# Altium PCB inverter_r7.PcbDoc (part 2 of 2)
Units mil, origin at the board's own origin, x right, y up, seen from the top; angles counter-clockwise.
Board outline 7000 x 5200 mil, 2 copper layers (Top Layer, Bottom Layer), stack 92.8 mil thick; 90 components, 75 nets, 259 pads, 1172 vias.
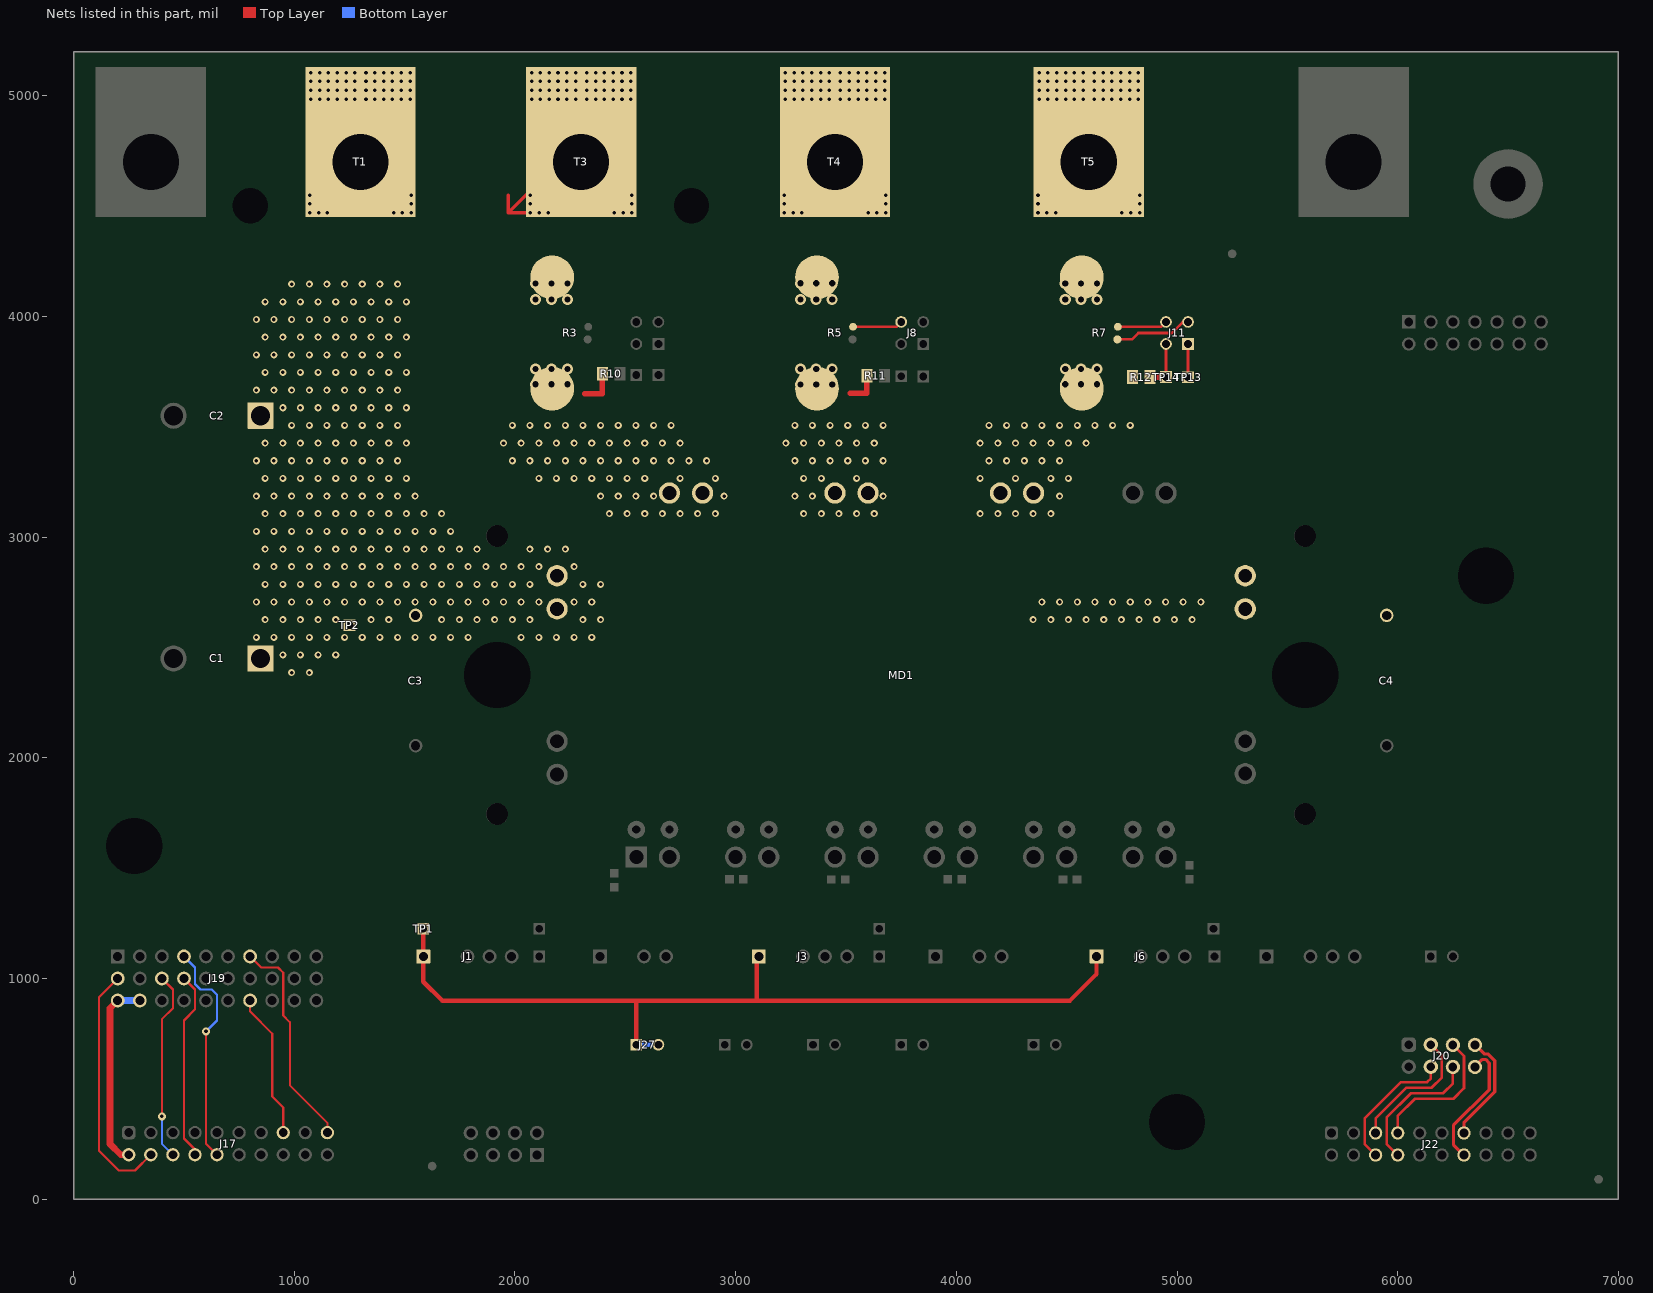
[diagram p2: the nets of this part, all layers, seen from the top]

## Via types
v1: diameter 32, hole 16, Top Layer to Bottom Layer, tented both sides, 762 vias
v2: diameter 32, hole 16, Top Layer to Bottom Layer, 369 vias
v3: diameter 50, hole 28, Top Layer to Bottom Layer, 36 vias
v4: diameter 36, hole 16, Top Layer to Bottom Layer, 5 vias

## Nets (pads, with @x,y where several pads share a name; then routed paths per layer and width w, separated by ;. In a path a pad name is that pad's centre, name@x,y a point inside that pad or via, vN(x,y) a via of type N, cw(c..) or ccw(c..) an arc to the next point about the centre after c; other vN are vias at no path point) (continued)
NetJ8_4: J8.4 R5.1 | length 227.2
  Top Layer w12: R5.1@3531.96,3952.81 3727.81,3952.81 J8.4@3750,3975
NetJ11_1: J11.1 TP13.1 | length 150.8
  Top Layer w15: TP13.1@5050,3724.21 J11.1@5050,3875
NetJ11_2: J11.2 R7.2 | length 353.1
  Top Layer w12: R7.2@4729.62,3896.09 4796.09,3896.09 4825,3925 4976.69,3925 5026.69,3975 J11.2@5050,3975
NetJ11_3: J11.3 R12.2 TP14.1 | length 222.7
  Top Layer w15: TP14.1@4950,3725 J11.3@4950,3875
  Top Layer w25: R12.2@4877.28,3725 TP14.1@4950,3725
NetJ11_4: J11.4 R7.1 | length 227.2
  Top Layer w12: R7.1@4731.96,3952.81 4927.81,3952.81 J11.4@4950,3975
NetMD1_19: MD1.19 MD1.20 R7.4 R12.1
  other v1: 4108,3106 4188,3106 4268,3106 4348,3106 4428,3106 4468,3186 4108,3266 4268,3266 4428,3266 4508,3266 4148,3346 4228,3346 4308,3346 4388,3346 4468,3346 4108,3426 4188,3426 4268,3426 4348,3426 4428,3426 4508,3426 4588,3426 4148,3506 4228,3506 4308,3506 4388,3506 4468,3506 4548,3506 4628,3506 4708,3506 4788,3506
  other v3: 4493.7,3692.46 4565.17,3692.46 4637.65,3692.46 4493.7,3761.48 4565.17,3761.48 4637.65,3761.48
NetMD1_21: MD1.21 MD1.22 R5.4 R11.1 | length 154.9
  Top Layer w25: 3518.49,3652.6 3595,3652.6 R11.1@3595,3730.95
  other v1: 3308,3106 3388,3106 3468,3106 3548,3106 3628,3106 3268,3186 3348,3186 3668,3186 3308,3266 3388,3266 3548,3266 3268,3346 3348,3346 3428,3346 3508,3346 3588,3346 3668,3346 3228,3426 3308,3426 3388,3426 3468,3426 3548,3426 3628,3426 3268,3506 3348,3506 3428,3506 3508,3506 3588,3506 3668,3506
  other v3: 3293.53,3690.95 3365,3690.95 3437.48,3690.95 3293.45,3761.48 3364.92,3761.48 3437.4,3761.48
NetMD1_23: MD1.23 MD1.24 R3.4 R10.1 | length 171.5
  Top Layer w25: 2315.23,3649.77 2396.5,3649.77 R10.1@2396.5,3740
  other v1: 2428,3106 2508,3106 2588,3106 2668,3106 2748,3106 2828,3106 2908,3106 2388,3186 2468,3186 2548,3186 2628,3186 2948,3186 2108,3266 2188,3266 2268,3266 2348,3266 2428,3266 2508,3266 2588,3266 2748,3266 2908,3266 1988,3346 2068,3346 2148,3346 2228,3346 2308,3346 2388,3346 2468,3346 2548,3346 2628,3346 2708,3346 2788,3346 2868,3346 1948,3426 2028,3426 2108,3426 2188,3426 2268,3426 2348,3426 2428,3426 2508,3426 2588,3426 2668,3426 2748,3426 1988,3506 2068,3506 2148,3506 2228,3506 2308,3506 2388,3506 2468,3506 2548,3506 2628,3506 2708,3506
  other v3: 2093.49,3692.46 2164.96,3692.46 2237.44,3692.46 2093.49,3761.48 2164.96,3761.48 2237.44,3761.48
NetR3_3: R3.3 T3.1 | length 970.5
  Top Layer w15: 1970,4550 1970,4510 1970,4470 ; T3.1@2050,4470 2010,4470 1970,4470 ; T3.1@2350,4470 2390,4470 T3.1@2430,4470 ; T3.1@2430,4550 2430,4510 T3.1@2430,4470 ; 1970,4470 2200,4700 T3.1@2430,4470
  other v2: 2070,4470 2110,4470 2150,4470 2450,4470 2490,4470 2530,4470 2070,4510 2530,4510 2070,4550 2530,4550 2075,4985 2115,4985 2155,4985 2195,4985 2235,4985 2275,4985 2325,4985 2365,4985 2405,4985 2445,4985 2485,4985 2525,4985 2075,5025 2115,5025 2155,5025 2195,5025 2235,5025 2275,5025 2325,5025 2365,5025 2405,5025 2445,5025 2485,5025 2525,5025 2075,5065 2115,5065 2155,5065 2195,5065 2235,5065 2275,5065 2325,5065 2365,5065 2405,5065 2445,5065 2485,5065 2525,5065 2075,5105 2115,5105 2155,5105 2195,5105 2235,5105 2275,5105 2325,5105 2365,5105 2405,5105 2445,5105 2485,5105 2525,5105
  other v3: 2093.49,4077.15 2164.96,4077.15 2237.44,4077.15 2093.49,4149.84 2164.96,4149.84 2237.44,4149.84
NetR5_3: R5.3 T4.1
  other v2: 3220,4470 3260,4470 3300,4470 3600,4470 3640,4470 3680,4470 3220,4510 3680,4510 3220,4550 3680,4550 3225,4985 3265,4985 3305,4985 3345,4985 3385,4985 3425,4985 3475,4985 3515,4985 3555,4985 3595,4985 3635,4985 3675,4985 3225,5025 3265,5025 3305,5025 3345,5025 3385,5025 3425,5025 3475,5025 3515,5025 3555,5025 3595,5025 3635,5025 3675,5025 3225,5065 3265,5065 3305,5065 3345,5065 3385,5065 3425,5065 3475,5065 3515,5065 3555,5065 3595,5065 3635,5065 3675,5065 3225,5105 3265,5105 3305,5105 3345,5105 3385,5105 3425,5105 3475,5105 3515,5105 3555,5105 3595,5105 3635,5105 3675,5105
  other v3: 3293.45,4077.25 3364.92,4077.25 3437.4,4077.25 3293.45,4150 3364.92,4150 3437.4,4150
NetR7_3: R7.3 T5.1
  other v2: 4370,4470 4410,4470 4450,4470 4750,4470 4790,4470 4830,4470 4370,4510 4830,4510 4370,4550 4830,4550 4375,4985 4415,4985 4455,4985 4495,4985 4535,4985 4575,4985 4625,4985 4665,4985 4705,4985 4745,4985 4785,4985 4825,4985 4375,5025 4415,5025 4455,5025 4495,5025 4535,5025 4575,5025 4625,5025 4665,5025 4705,5025 4745,5025 4785,5025 4825,5025 4375,5065 4415,5065 4455,5065 4495,5065 4535,5065 4575,5065 4625,5065 4665,5065 4705,5065 4745,5065 4785,5065 4825,5065 4375,5105 4415,5105 4455,5105 4495,5105 4535,5105 4575,5105 4625,5105 4665,5105 4705,5105 4745,5105 4785,5105 4825,5105
  other v3: 4493.49,4077.25 4564.96,4077.25 4637.44,4077.25 4493.49,4149.84 4564.96,4149.84 4637.44,4149.84
nFLT1_H: J17.6 J19.8 | length 860.6
  Top Layer w10: v4(400,375) 400,815 450,865 450,950 J19.8@400,1000
  Bottom Layer w10: v4(400,375) 400,251.52 J17.6@450,201.52
nFLT1_L: J17.8 J19.11 | length 860.6
  Top Layer w10: J19.11@500,1000 550,950 550,860 500,810 500,275 550,225 J17.8@550,201.52
nFLT2_H: J17.4 J19.2 | length 1117.5
  Top Layer w10: J19.2@200,1000 115,915 115,219.35 204.35,130 278.48,130 J17.4@350,201.52
nFLT2_L: J17.10 J19.10 | length 1031.9
  Top Layer w10: v4(600,760) 600,251.52 J17.10@650,201.52
  Bottom Layer w10: J19.10@500,1100 550,1050 550,975 575,950 626.05,950 650,926.05 650,810 v4(600,760)
OVP: J20.4 J22.6 | length 613.9
  Top Layer w12: J22.6@5900,200 5850,250 5850,365.01 6014.99,530 6132.74,530 6150,547.26 J20.4@6150,600
SDI: J17.15 J19.21 | length 660.6
  Top Layer w10: J19.21@800,900 800,850 900,750 900,465 950,415 J17.15@950,301.52
SDO: J17.19 J19.19 | length 988.2
  Top Layer w10: J19.19@800,1100 850,1050 926.41,1050 950,1026.41 950,831.81 980,801.81 980,515.78 1150,345.78 J17.19@1150,301.52
VCC1: J17.2 J19.3 J19.6 | length 869.6
  Top Layer w30: J19.3@200,900 165,865 165,250 213.48,201.52 J17.2@250,201.52
  Bottom Layer w30: J19.3@200,900 J19.6@300,900
Vdc_N: J20.8 J22.14 | length 588.6
  Top Layer w15: J22.14@6300,200 6252.38,247.62 6252.38,334.19 6414.31,496.12 6414.31,616.68 6397.99,633 6384,633 J20.8@6350,599
Vdc_P: J20.7 J22.13 | length 503.9
  Top Layer w15: J22.13@6300,300 6300,346.45 6439.31,485.76 6439.31,627.04 6408.34,658 6391,658 J20.7@6350,699
Vdcbus: C1.1 C2.1 C3.1 C4.1 MD1.15 MD1.16 MD1.25 MD1.26 T1.1 TP2.1
  other v1: 988,2386 1068,2386 948,2466 1028,2466 1108,2466 1188,2466 828,2546 908,2546 988,2546 1068,2546 1148,2546 1228,2546 1308,2546 1388,2546 1468,2546 1548,2546 1628,2546 1708,2546 1788,2546 2028,2546 2108,2546 2188,2546 2268,2546 2348,2546 868,2626 948,2626 1028,2626 1108,2626 1188,2626 1348,2626 1428,2626 1668,2626 1748,2626 1828,2626 1908,2626 1988,2626 2068,2626 2308,2626 2388,2626 4348,2626 4428,2626 4508,2626 4588,2626 4668,2626 4748,2626 4828,2626 4908,2626 4988,2626 5068,2626 828,2706 908,2706 988,2706 1068,2706 1148,2706 1228,2706 1308,2706 1388,2706 1468,2706 1548,2706 1628,2706 1708,2706 1788,2706 1868,2706 1948,2706 2028,2706 2108,2706 2268,2706 2348,2706 4388,2706 4468,2706 4548,2706 4628,2706 4708,2706 4788,2706 4868,2706 4948,2706 5028,2706 5108,2706 868,2786 948,2786 1028,2786 1108,2786 1188,2786 1268,2786 1348,2786 1428,2786 1508,2786 1588,2786 1668,2786 1748,2786 1828,2786 1908,2786 1988,2786 2068,2786 2308,2786 2388,2786 828,2866 908,2866 988,2866 1068,2866 1148,2866 1228,2866 1308,2866 1388,2866 1468,2866 1548,2866 1628,2866 1708,2866 1788,2866 1868,2866 1948,2866 2028,2866 2108,2866 2268,2866 868,2946 948,2946 1028,2946 1108,2946 1188,2946 1268,2946 1348,2946 1428,2946 1508,2946 1588,2946 1668,2946 1748,2946 1828,2946 2068,2946 2148,2946 2228,2946 828,3026 908,3026 988,3026 1068,3026 1148,3026 1228,3026 1308,3026 1388,3026 1468,3026 1548,3026 1628,3026 1708,3026 868,3106 948,3106 1028,3106 1108,3106 1188,3106 1268,3106 1348,3106 1428,3106 1508,3106 1588,3106 1668,3106 828,3186 908,3186 988,3186 1068,3186 1148,3186 1228,3186 1308,3186 1388,3186 1468,3186 1548,3186 868,3266 948,3266 1028,3266 1108,3266 1188,3266 1268,3266 1348,3266 1428,3266 1508,3266 828,3346 908,3346 988,3346 1068,3346 1148,3346 1228,3346 1308,3346 1388,3346 1468,3346 868,3426 948,3426 1028,3426 1108,3426 1188,3426 1268,3426 1348,3426 1428,3426 1508,3426 988,3506 1068,3506 1148,3506 1228,3506 1308,3506 1388,3506 1468,3506 948,3586 1028,3586 1108,3586 1188,3586 1268,3586 1348,3586 1428,3586 1508,3586 828,3666 908,3666 988,3666 1068,3666 1148,3666 1228,3666 1308,3666 1388,3666 1468,3666 868,3746 948,3746 1028,3746 1108,3746 1188,3746 1268,3746 1348,3746 1428,3746 1508,3746 828,3826 908,3826 988,3826 1068,3826 1148,3826 1228,3826 1308,3826 1388,3826 1468,3826 868,3906 948,3906 1028,3906 1108,3906 1188,3906 1268,3906 1348,3906 1428,3906 1508,3906 828,3986 908,3986 988,3986 1068,3986 1148,3986 1228,3986 1308,3986 1388,3986 1468,3986 868,4066 948,4066 1028,4066 1108,4066 1188,4066 1268,4066 1348,4066 1428,4066 1508,4066 988,4146 1068,4146 1148,4146 1228,4146 1308,4146 1388,4146 1468,4146
  other v2: 1070,4470 1110,4470 1150,4470 1450,4470 1490,4470 1530,4470 1070,4510 1530,4510 1070,4550 1530,4550 1075,4985 1115,4985 1155,4985 1195,4985 1235,4985 1275,4985 1325,4985 1365,4985 1405,4985 1445,4985 1485,4985 1525,4985 1075,5025 1115,5025 1155,5025 1195,5025 1235,5025 1275,5025 1325,5025 1365,5025 1405,5025 1445,5025 1485,5025 1525,5025 1075,5065 1115,5065 1155,5065 1195,5065 1235,5065 1275,5065 1325,5065 1365,5065 1405,5065 1445,5065 1485,5065 1525,5065 1075,5105 1115,5105 1155,5105 1195,5105 1235,5105 1275,5105 1325,5105 1365,5105 1405,5105 1445,5105 1485,5105 1525,5105
Vdcbus_Jumped: J1.1 J3.1 J6.1 J27.1 J27.2 TP1.1 | length 3956
  Top Layer w20: TP1.1@1585,1225 J1.1@1585,1100 1585,985.01 1670.01,900 ; 1671.01,900 2550,900 ; J27.1@2550,700 2550,900 ; J3.1@3095,1100 3095,905 3100,900 ; J6.1@4635,1100 4635,1020 4515,900 3100,900 ; 2550,900 3100,900
  Bottom Layer w20: J27.1@2550,700 J27.2@2650,700
VinvA: J20.5 J22.7 | length 646.1
  Top Layer w12: J22.7@6000,300 6000,377.2 6077.8,455 6252.15,455 6300,502.85 6300,649 J20.5@6250,699
VinvB: J20.6 J22.8 | length 628.9
  Top Layer w12: J22.8@6000,200 5950,250 5950,369.99 6060.01,480 6204.94,480 6250,525.06 J20.6@6250,599
VinvC: J20.3 J22.5 | length 611.7
  Top Layer w12: J22.5@5900,300 5900,365.01 6040.18,505.18 6154.16,505.18 6199.99,551.02 6199.99,650.01 J20.3@6150,700
pads on no net: FID1.1 FID2.1 FID3.1 J17.20 J19.1 J19.22 J19.23 MD1. MH1.1 MH2.1 MH3.1 MH4.1 MH5.1

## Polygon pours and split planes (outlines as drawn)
NetR3_3 on Top Layer "TOP_LAYER_NETR3_3_P006" (solid, pour order 6): 2000,5150 1948,5096.77 1948,4115 2029.73,4033.27 2277.09,4033.27 2277.09,4157.28 2500,4157.54 2624.41,4258.58 2624.41,5100.59 2575,5150
+3V3 on Top Layer "TOP_LAYER_+3V3_P063" (solid, remove dead copper, pour order 63): 5635,186.01 5706,115 5815,115 5839.31,134.71 5839.31,401.31 5985.27,547.26 6065.27,547.26 6102,583.99 6100,585.99 6100,715 5975.69,715 5635,374.31
5V on Top Layer "TOP_LAYER_5V_P059" (solid, remove dead copper, pour order 59): 6950,3500 6950,4025.9 6900.9,4075 6649.51,4075 6625,4050.49 6625,3775 6650,3775 6925,3500
NetH1_1 on Top Layer "TOP_LAYER_NETH1_1_P057" (solid, remove dead copper, pour order 57): 5550,4325 6662.87,4325 6765,4450 6765,5070 6682.75,5152.25 5537.25,5152.25 5450,5065 5450,4425
NetMD1_19 on Top Layer "TOP_LAYER_NETMD1_19_P054" (solid, remove dead copper, pour order 54): 4098.81,3075 4448.91,3075 4551.1,3177.2 4551.1,3278.28 4551.1,3327.2 4676.1,3452.2 4776.1,3452.2 4826.1,3502.2 4826.1,3664.98 4796.17,3694.91 4677.96,3694.91 4677.96,3818.93 4355.23,3818.93 4055.23,3518.93 4055.23,3127.2
5V on Top Layer "TOP_LAYER_5V_P048" (solid, remove dead copper, pour order 48): 1145.02,1170 1090,1170 1050,1130 1050,650 1200,500 1525,175 1625,75 5749.64,75 5624.64,149.86 4300.14,149.86 4048,402 2248,402 2125,525 1675,525 1450,750 1293.36,750 1170,873.36 1170,1145.02
no net on Top Layer "TOP_LAYER_NONET_P044" (solid, remove dead copper, pour order 44): 1554.49,340.78
Vdcbus on Top Layer "TOP_LAYER_VDCBUS_P034" (solid, remove dead copper, pour order 34): 1550,5150 1025,5150 975,5100 975,4228.16 750,4003.16 750,2350 800,2300 1100,2300 1275,2475 5925,2475 6000,2550 6000,2850 5750,3100 5300,3100 5075,2875 2372.23,2875 2250,3000 1815.27,3000 1550,3263.13 1550,4063 1600,4138 1600,5100
HV_GND on Top Layer "TOP_LAYER_HV_GND_P030" (solid, remove dead copper, pour order 30): 80.76,5150 50,5119.24 50,4498.12 50,1700 196.8,1553.2 1942.92,1553.2 1999.73,1610 2155,1610 2445,1900 4964.58,1900 5249.67,1700 5800,1700 6000,1900 6000,2199.99 5924.99,2275 1375,2275 1200,2100 721.84,2100 577.54,2244.3 577.54,4080.7 650,4153.16 650,5115 615,5150
NetR7_3 on Top Layer "TOP_LAYER_NETR7_3_P010" (solid, pour order 10): 4300,5150 4250,5100 4250,4149.71 4366.44,4033.27 4677.09,4033.27 4677.09,4157.28 4869.05,4157.28 4930,4218.23 4930,5120 4900,5150
NetR5_3 on Top Layer "TOP_LAYER_NETR5_3_P008" (solid, pour order 8): 3150.01,5150.01 3100,5100 3100,4147.28 3214.02,4033.27 3477.09,4033.27 3477.09,4157.28 3670.3,4157.28 3775,4261.99 3775,5100.01 3725,5150.01
NetMD1_21 on Top Layer "TOP_LAYER_NETMD1_21_P002" (solid, remove dead copper, pour order 2): 3200,3816.73 3154.12,3770.86 3154.13,3420.87 3225,3350 3225,3125 3275,3075 3675,3075 3725,3125 3725,3602.09 3634.37,3692.72 3472.84,3692.72 3472.84,3816.73
NetMD1_23 on Top Layer "TOP_LAYER_NETMD1_23_P000" (solid, remove dead copper, pour order 0): 1975,3816.73 1923.42,3765.15 1923.42,3380.64 2106.25,3197.8 2300.23,3197.8 2423.03,3075 2930,3075 2975,3120 2975,3284.13 2709.13,3550 2605,3550 2462.28,3692.72 2277.09,3692.72 2277.09,3816.73
5V_GND on Bottom Layer "BOTTOM_LAYER_5V_GND_P061" (solid, remove dead copper, pour order 61): 6950,3500 6950,4025 6900,4075 6524.51,4075 6500,4050.49 6500,3875 6550,3875 6925,3500
NetH1_1 on Bottom Layer "BOTTOM_LAYER_NETH1_1_P055" (solid, remove dead copper, pour order 55): 5550,4325 6291.48,4325 6662.87,4325 6765,4450 6765,5070 6682.75,5152.25 5537.25,5152.25 5450,5065 5450,4425
DGND on Bottom Layer "BOTTOM_LAYER_DGND_P050" (solid, remove dead copper, pour order 50): 200,900 149.35,900 149.35,897.04 100,847.69 100,179.35 179.35,100 1200,100 1247.57,147.57 1255,147.57 1255,385 1190,450 915,725 915,904.45 869.45,950 250,950
5V_GND on Bottom Layer "BOTTOM_LAYER_5V_GND_P038" (solid, remove dead copper, pour order 38): 1030,1170 970,1170 950,1150 950,750 1200,500 1525,175 1625,75 2175,75 5747.14,75 5627.14,149.86 4300.65,149.86 4049.5,400 2250,400 2125,525 1675,525 1374.02,825.98 1073.96,825.98 1050,849.94 1050,1150
AGND on Bottom Layer "BOTTOM_LAYER_AGND_P036" (solid, remove dead copper, pour order 36): 5973.2,715 5650,415.51 5650,170.96 5691.55,129.49 6875,150.44 6875,3450 6475,3850 6475,4050.49 6450.49,4075 5995,4075 5950,4030 5950,3780 6600,3130 6600,861.81 6453.19,715
HV_GND on Bottom Layer "BOTTOM_LAYER_HV_GND_P032" (solid, remove dead copper, pour order 32): 80.76,5150 50,5119.24 50,1700 196.8,1553.2 2093.2,1553.2 2440,1900 4963.78,1900 5249.67,1700 5800,1700 6000,1900 6000,2200 5924.98,2275 1375,2275 1200,2100 721.84,2100 577.54,2244.3 577.54,4080.7 650,4153.16 650,5115 615,5150
Vdcbus on Bottom Layer "BOTTOM_LAYER_VDCBUS_P024" (solid, remove dead copper, pour order 24): 1550,5150 1025,5150 975,5100 975,4228.16 750,4003.16 750,2350 800,2300 1100,2300 1275,2475 5925,2475 6000,2550 6000,2850 5750,3100 5300,3100 5075,2875 2372.23,2875 2250,3000 1815.27,3000 1550,3263.13 1550,4063 1600,4138 1600,5100.04
NetMD1_19 on Bottom Layer "BOTTOM_LAYER_NETMD1_19_P022" (solid, remove dead copper, pour order 22): 4098.81,3075 4448.91,3075 4551.1,3177.2 4551.1,3327.2 4676.1,3452.2 4776.1,3452.2 4826.1,3502.2 4826.1,3664.98 4796.17,3694.91 4677.09,3694.91 4677.09,3818.93 4355.23,3818.93 4055.23,3518.93 4055.23,3127.2
NetMD1_21 on Bottom Layer "BOTTOM_LAYER_NETMD1_21_P020" (solid, remove dead copper, pour order 20): 3200,3816.73 3154.12,3770.86 3154.13,3420.87 3225,3350 3225,3125 3275,3075 3675,3075 3725,3125 3725,3602.09 3634.37,3692.72 3472.84,3692.72 3472.84,3816.73
NetMD1_23 on Bottom Layer "BOTTOM_LAYER_NETMD1_23_P018" (solid, remove dead copper, pour order 18): 1975,3816.73 1923.42,3765.15 1923.42,3380.64 2105.15,3198.9 2299.13,3198.9 2423.03,3075 2930,3075 2975,3120 2975,3284.13 2709.13,3550 2605,3550 2462.28,3692.72 2277.09,3692.72 2277.09,3816.73
NetR7_3 on Bottom Layer "BOTTOM_LAYER_NETR7_3_P016" (solid, pour order 16): 4300,5150 4250,5100 4250,4150.66 4367.4,4033.27 4677.09,4033.27 4677.09,4157.28 4869.05,4157.28 4930,4218.23 4930,5120 4899.99,5150
NetR5_3 on Bottom Layer "BOTTOM_LAYER_NETR5_3_P014" (solid, pour order 14): 3150.01,5150.01 3100,5100 3100,4147.28 3214.02,4033.27 3477.09,4033.27 3477.09,4157.28 3670.3,4157.28 3775,4261.99 3775,5100.01 3725.01,5150
NetR3_3 on Bottom Layer "BOTTOM_LAYER_NETR3_3_P012" (solid, pour order 12): 2000,5150 1948,5096.77 1948,4115 2029.73,4033.27 2277.09,4033.27 2277.09,4157.28 2500,4157.54 2624.41,4258.58 2624.41,5100.59 2575,5150

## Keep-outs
Keep-Out Layer:
  text ".Layer_Name" at 577,-858.49 h60

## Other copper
Top Layer:
  text ".Layer_Name" at 577,-858.49 h60
Bottom Layer:
  text ".Layer_Name" at 577,-858.49 h60

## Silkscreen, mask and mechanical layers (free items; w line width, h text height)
Top Overlay:
  lines w6: 75,1000 75,1811.42 6325,1811.42 ; 1225,1000 6325,1000 6325,1410 6325,1759.63 6325,1810 ; 2400,499.35 2400,800 6454.13,800 6454.13,499.35 5100,500 ; 2400,500 3600,500 4900,500 ; 2400,3782.48 2400,4200 3235,4200 ; 2401.09,3781.97 3222.6,3781.97 ; 3558.23,3780 4440.5,3780 ; 3558.23,4200 4440.5,4200 ; 4758.03,4200 6800,4200 6800,3775 4780.55,3773.91
  lines w10: 1255,2450 1340,2450 ; 1290,3550 1380,3550 ; 1300,2411.45 1300,2488.55 ; 1335,3511.45 1335,3595.26
  lines w20: 50,4225 225,4225 1650,4225 1650,5150 ; 5000,5150 5000,4305 1850,4305 1850,5150 ; 1850,5150 1850,5150
  lines w40: 100,1350 1325,1350 1325,877 1827,375 4810.04,375 ; 5200,375.36 5324.64,375.36 5800,850 5843.81,893.81 6325,893.81 6400.2,969.01 6400.21,1850 ; 6400,1850 6400,2650 ; 6400,3000 6400,3080.21 5750,3735 5750,4250 5750,4325 6950,4325
  text "HOT SURFACE" at 4247.67,5127 h72.83 r180
  text "HIGH VOLTAGE" at 3098.28,5125 h72.83 r180
  text "CAUTION" at 4206.99,5040 h90 r180
  text "DANGER" at 3035,5035 h100 r180
  text "VOUT-A" at 2000,4600 h72.83 r90
  text "VOUT-B" at 3150,4600 h72.83 r90
  text "VOUT-C" at 4300,4600 h72.83 r90
  text "EARTH" at 5500,4595.71 h72.83 r90
  text "DC -" at 495.6,4425 h80 r180
  text "DC +" at 1331,4425 h80 r180
  text "HIGH VOLTAGE" at 6331.88,4415 h80 r180
  text "AC OUTPUT --> Max 25A sine (rms)" at 4268,4400 h90 r180
  text "-->  450Vdc / 25A" at 915.97,4317.23 h72.83 r180
  text "DC INPUT" at 1262,4317.23 h72.83 r180
  text "LOW VOLTAGE" at 6328,4280 h80 r180
  text "Slot for Current Sense Board" at 5665.34,4162.21 h72.83 r180
  text "IsoC_15V-" at 4950,3599.98 h50 r270
  text "IsoC_15V+" at 5050,3599.98 h50 r270
  text "IsoB_15V-" at 3740,3598.34 h50 r270
  text "IsoB_15V+" at 3840,3598.34 h50 r270
  text "IsoA_15V+" at 2635,3588 h50
  text "IsoA_15V-" at 2382,3587 h50
  text "LOW VOLTAGE" at 5990,3555 h80 r315
  text "HIGH VOLTAGE" at 5895,3455 h80 r315
  text "'.PRJ_Number'.PCB_Rev" at 3919.5,2650 h70 r180
  text "TRACTION INVERTER" at 3933.5,2550 h120 r180
  text "HIGH VOLTAGE" at 6305,2510 h80 r270
  text "LOW VOLTAGE" at 6440,2510 h80 r270
  text "DANGER - HIGH VOLTAGE" at 3562.5,2253 h100 r180
  text "READ USER GUIDE BEFORE USE" at 5375,2250 h100 r180
  text "AL" at 3125,1800 h72.83 r180
  text "AH" at 2670,1795 h72.83 r180
  text "BH" at 3565,1795 h72.83 r180
  text "BL" at 4014.15,1795 h72.83 r180
  text "CH" at 4475,1795 h72.83 r180
  text "CL" at 4915,1790 h72.83 r180
  text "HIGH VOLTAGE" at 980,1445 h80 r180
  text "Slot for Inverter Gate Driver Board" at 4075,1385 h72.83 r180
  text "LOW VOLTAGE" at 970,1300 h80 r180
  text "IsoA_15V+" at 2220,1297.57 h50 r180
  text "IsoB_15V+" at 3750,1290 h50 r180
  text "IsoC_15V+" at 5270,1290 h50 r180
  text "IsoA_15V-" at 2215.94,980 h50 r180
  text "IsoB_15V-" at 3750,980 h50 r180
  text "IsoC_15V-" at 5270,975 h50 r180
  text "HIGH VOLTAGE" at 6305,975 h80 r180
  text "LOW VOLTAGE" at 6380,861.81 h80 r180
  text "Slot for Voltage Sense Board" at 5490,745 h72.83 r180
  text "HIGH VOLTAGE" at 1825,510 h80 r135
  text "HIGH VOLTAGE" at 3101.18,465 h80 r180
  text "HIGH VOLTAGE" at 4815.04,465 h80 r180
  text "LOW VOLTAGE" at 1726.01,410 h80 r135
  text "LOW VOLTAGE" at 3101.18,330 h80 r180
  text "LOW VOLTAGE" at 4810.04,325.49 h80 r180
  text ".Layer_Name" at 577,-858.49 h60
Bottom Overlay:
  text ".Layer_Name" at 577,-858.49 h60
Top Paste:
  text ".Layer_Name" at 577,-858.49 h60
Bottom Paste:
  text ".Layer_Name" at 577,-858.49 h60
Top Solder:
  text ".Layer_Name" at 577,-858.49 h60
  text ".Layer_Name" at 577,-858.49 h60
Bottom Solder:
  text ".Layer_Name" at 577,-858.49 h60
Drill Guide:
  text ".Layer_Name" at 577,-858.49 h60
M1 Board Outline:
  the board outline again, w10
  text ".Layer_Name" at 577,-858.49 h60
M2 Board Dimensions:
  rectangle: 0,-275 125,-150
  rectangle: 125,-400 500,-275
  lines w7: 0,-275 1000,-275 ; 125,-400 125,-150 ; 250,-400 250,-150 ; 500,-400 500,-150 ; 750,-400 750,-150 ; 0,-400 1000,-400 1000,-150 0,-150 0,-400
  text ".Layer_Name" at 577,-858.49 h60
M3 3D STEP Top:
  text ".Layer_Name" at 577,-858.49 h60
M4 3D STEP Bottom:
  text ".Layer_Name" at 577,-858.49 h60
M5 Assembly Top:
  lines w10: -292,-930.17 6308,-930.17 ; -292,-726.83 6310,-726.83 ; -292,-523.5 -292,-1133.5 3713,-1133.5 6310,-1133.5 6310,-523.5 -291.5,-523.5 -291.5,-1133.5 1284,-1133.5 ; 2173,-1133.5 2173,-523.5 ; 3440,-726.83 3440,-523.5 ; 4280,-726.83 4280,-523.5 ; 4902,-1140 4902,-937.17
  text "COMPONENTS MARKED 'DNP' SHOULD NOT BE POPULATED." at 1153.5,-318.5 h60
  text "ASSEMBLY VARIANT:" at 1153,-434 h60
  text ".VariantName" at 2189,-434 h60
  text "PCB VIEWED FROM TOP SIDE" at -228.5,-655.67 h60
  text "BOARD #:" at 2248,-655.67 h60
  text ".PRJ_Number" at 2793.5,-655.67 h60
  text "REV:" at 3638,-655.67 h60
  text ".PCB_Rev" at 3929.5,-655.67 h60
  text "SVN REV:" at 4476,-655.67 h60
  text ".VersionControl_RevNumber" at 4982,-655.67 h60
  text "TID #:" at 2248,-859 h60
  text ".TID" at 2793.5,-859 h60
  text "PLOT NAME =" at -228.5,-1064.34 h60
  text ".plot_File_Name" at 577,-1064.34 h60
  text "GENERATED    :" at 2250,-1064.34 h60
  text ".Print_Date" at 3119.5,-1064.34 h60
  text ".Print_Time" at 3848.5,-1064.34 h60
  text "TEXAS INSTRUMENTS" at 5113,-1064.34 h60
M6 Assembly Bottom:
  lines w10: -292.5,-727.33 6309.5,-727.33 ; -290.5,-930.67 6309.5,-930.67 ; 1115.5,-1140.5 1115.5,-937.67 ; 1737.5,-727.33 1737.5,-524 ; 2577.5,-727.33 2577.5,-524 ; 3844.5,-1134 3844.5,-524 ; 4733.5,-1134 6309,-1134 6309,-524 -292.5,-524 -292.5,-1134 2304.5,-1134 6309.5,-1134 6309.5,-524
  text "COMPONENTS MARKED 'DNP' SHOULD NOT BE POPULATED." at 6102,-318 h60
  text ".VariantName" at 5058,-434 h60
  text "ASSEMBLY VARIANT:" at 6097,-434 h60
  text ".VersionControl_RevNumber" at 1035.5,-656.17 h60
  text "SVN REV:" at 1541.5,-656.17 h60
  text ".PCB_Rev" at 2088,-656.17 h60
  text "REV:" at 2379.5,-656.17 h60
  text ".PRJ_Number" at 3224,-656.17 h60
  text "BOARD #:" at 3769.5,-656.17 h60
  text "PCB VIEWED FROM BOTTOM SIDE" at 6246,-656.17 h60
  text ".TID" at 3224,-859.5 h60
  text "TID #:" at 3769.5,-859.5 h60
  text "TEXAS INSTRUMENTS" at 904.5,-1064.84 h60
  text ".Print_Time" at 2169,-1064.84 h60
  text ".Print_Date" at 2898,-1064.84 h60
  text "GENERATED    :" at 3767.5,-1064.84 h60
  text ".plot_File_Name" at 5440.5,-1064.84 h60
  text "PLOT NAME =" at 6246,-1064.84 h60
M9 Title Sheet:
  drawing of 57 lines, arcs and shapes, not listed
  text "1" at 739.84,8036.5 h70
  text "2" at 3235.5,8036.5 h70
  text "3" at 5724.84,8036.5 h70
  text "4" at 8231.51,8036.5 h70
  text "5" at 10730.5,8036.5 h70
  text "6" at 13235.5,8036.5 h70
  text "A" at -416.5,6893.5 h70
  text "A" at 14383.5,6893.5 h70
  text "B" at -416.5,4513.5 h70
  text "B" at 14383.5,4513.5 h70
  text "C" at -416.5,2138.5 h70
  text "C" at 14383.5,2138.5 h70
  text "PROJECT TITLE:" at 11343.5,277.5 h45
  text ".PRJ_Title" at 11393.5,144.17 h70
  text "DESIGNED FOR:" at 11343.5,-23.5 h45
  text ".PRJ_Customer" at 11393.5,-163.5 h70
  text "D" at -416.5,-231.5 h70
  text "D" at 14383.5,-231.5 h70
  text "FILE NAME:" at 11343.5,-323.5 h45
  text ".PCB_File_Name_No_Path" at 11393.5,-443.5 h70
  text "Texas Instruments (TI) and/or its licensors do not warrant the accuracy or completeness of this specification" at 6374,-605.34 h45
  text "ENGINEER:" at 11343.5,-613.5 h45
  text "LAYOUT BY:" at 12848.5,-613.5 h45
  text "or any information contained therein. TI and/or its licensors do not warrant that this design will meet" at 6329.01,-718 h45
  text ".PRJ_Engineer" at 11393.5,-768.49 h70
  text ".PCB_Layout" at 12899,-768.49 h70
  text "the specifications, will be suitable for your application or fit for any particular purpose, or will operate in" at 6329.01,-830.67 h45
  text ".Layer_Name" at 577,-858.49 h60
  text "ALTIUM DESIGNER VERSION:" at 12848.5,-923.5 h45
  text "an implementation. TI and/or its licensors do not warrant that the design is production worthy. You should" at 6329.01,-943.33 h45
  text "completely validate and test your design implementation to confirm the system functionality for your application." at 6374,-1056 h45
  text ".print_Scale" at 11393.5,-1056.83 h70
  text ".Application_BuildNumber" at 12899,-1056.83 h70
  text "1" at 739.84,-1263.5 h70
  text "2" at 3235.5,-1263.5 h70
  text "3" at 5724.84,-1263.5 h70
  text "4" at 8231.51,-1263.5 h70
  text "5" at 10730.5,-1263.5 h70
  text "6" at 13235.5,-1263.5 h70
M10 Fab Notes:
  drawing of 189 lines, arcs and shapes, not listed
  text "DESIGN INFORMATION" at 12382.02,6356.17 h60
  text "MIN. TRACK WIDTH:" at 11737.46,6224.05 h60
  text "8" at 12833.7,6224.05 h60
  text "MIL" at 12988.46,6224.05 h60
  text "MIN. CLEARANCE:" at 11737.46,6099.92 h60
  text "0.2" at 12773.7,6099.93 h60
  text "mm" at 12988.46,6099.92 h60
  text "MIN. VIA PAD SIZE:" at 11737.46,5975.8 h60
  text "24" at 12803.71,5975.8 h60
  text "MIL" at 12988.46,5975.8 h60
  text "0.05mm (2MIL)" at 12432.46,5845.9 h60
  text "MINIMUM ANNULAR RING" at 11408.23,5837.67 h60
  text "EXTERNAL" at 13140.46,5837.67 h60
  text "PER" at 11608.23,5727.55 h60
  text "IPC-D-275 CLASS 2 LEVEL C" at 11828.23,5727.54 h60
  text "MIL, HOLES" at 13316.46,5627.07 h60
  text "+/-" at 12924,5618.48 h60
  text "+/-" at 13778,5618.48 h60
  text "REGISTRATION TOLERANCES:" at 11408.23,5617.42 h60
  text "METAL" at 12608,5617.42 h60
  text "5" at 13184.2,5617.42 h60
  text "3" at 14017.2,5617.42 h60
  text "MIL" at 14133.46,5617.42 h60
  text "HOLE SIZE TOLERANCE (UNLESS OTHERWISE SPECIFIED):" at 11408.23,5519.1 h60
  text "+/-" at 13778,5516.23 h60
  text "3" at 14017.2,5515.17 h60
  text "MIL" at 14133.46,5515.17 h60
  text "MATERIAL:" at 11333.46,5377.52 h60
  text "FR-4 High Tg" at 12319.9,5249 h60
  text "X" at 12175.46,5241.01 h60
  text "FR-408" at 11754.46,5236.49 h60
  text "OTHER" at 13242.46,5236.49 h60
  text "X" at 11950,5100 h60
  text "93 MIL (2.4mm) +/-10%" at 12074.56,5093.46 h60
  text "THICKNESS:" at 11408.23,5085.24 h60
  text "OTHER" at 13359.46,5085.24 h60
  text "TOLERANCE:" at 11408.23,4946.92 h60
  text "X" at 12256.46,4946.92 h60
  text "ANSI IPC-6012 TYPE 3 CLASS 2" at 12434.48,4946.92 h60
  text "OTHER +/-" at 12434.46,4802.73 h60
  text "BOW & TWIST:" at 11408.23,4657.54 h60
  text "X" at 12256.46,4657.54 h60
  text "ANSI IPC-6012 TYPE 3 CLASS 2" at 12434.48,4657.54 h60
  text "OTHER +/-" at 12434.46,4510.85 h60
  text "DRILLING:" at 11333.46,4380.23 h60
  text "NC_DRILL FILES" at 13094.46,4275.04 h60
  text "REFERENCE:" at 11408.23,4271.1 h60
  text "X" at 12065.46,4271.01 h60
  text "AS SHOWN" at 12243.46,4271.1 h60
  text "X" at 12966.46,4271.1 h60
  text "OTHER" at 13392.46,4128.85 h60
  text "PTH COPPER THICKNESS:" at 11407.91,4125.32 h60
  text "X" at 12547.14,4125.32 h60
  text "20-30 um" at 12675.14,4125.32 h60
  text "BOARD FINISH:" at 11333.46,3977.73 h60
  text "SILKSCREEN:" at 11488.68,3867.6 h60
  text "X" at 12446.46,3867.6 h60
  text "TOP" at 12563.46,3867.6 h60
  text "BOTTOM" at 13074.46,3867.6 h60
  text "SILKSCREEN COLOR:" at 11488.68,3712.41 h60
  text "X" at 12445.46,3712.41 h60
  text "WHITE" at 12563.46,3712.41 h60
  text "OTHER" at 13074.46,3712.41 h60
  text "X" at 12576.46,3568.96 h60
  text "GREEN" at 12694.46,3568.96 h60
  text "OTHER" at 13312.46,3568.96 h60
  text "SOLDER RESIST COLOR:" at 11488.68,3562.1 h60
  text "X" at 12576.46,3414.71 h60
  text "MATTE" at 12694.46,3414.71 h60
  text "SEMI-GLOSS" at 13312,3414.07 h60
  text "IMMERSION GOLD (ENIG)" at 12394.46,3241.94 h60
  text "ENEPIG" at 13732,3234.72 h60
  text "SURFACE FINISH:" at 11333.46,3233.72 h60
  text "X" at 12225,3233.72 h60
  text "HASL LEAD FREE" at 13475,3100 h60
  text "IMM. TIN/SILVER OR EQUIV" at 11663,3096.4 h60
  text "OTHER" at 13094.46,3092.47 h60
  text "ARRAY/PANEL:" at 11333.46,2937.09 h60
  text "CUT AND TRIM PER M1 BOARD OUTLINE" at 12394.46,2928.87 h60
  text "N.C. ROUTE" at 12394.46,2792.9 h60
  text "X" at 13082.46,2792.9 h60
  text "V. SCORE" at 13260.46,2792.9 h60
  text "CERTIFICATION:" at 11333.46,2663.77 h60
  text "MATERIALS AND WORKMANSHIP FOR ALL PCBS" at 12058.46,2663.77 h60
  text "TO MEET OR EXCEED THE REQUIREMENTS OF:" at 12058.46,2569.71 h60
  text "X" at 11695.97,2441.08 h60
  text "ANSI IPC-A-600F CLASS ->" at 11823.96,2441.08 h60
  text "X" at 13471.97,2441.08 h60
  text "2" at 13581.96,2441.08 h60
  text "1" at 13266.96,2439.58 h60
  text "3" at 13935.96,2439.58 h60
  text "X" at 12507.97,2293.39 h60
  text "RoHS" at 12635.96,2293.39 h60
  text "OTHER" at 13280.36,2293.39 h60
  text "PER ORDER" at 13677.42,2293.39 h60
  text "ALL BOARDS MUST MEET OR EXCEED UL94-V0 REQUIREMENTS." at 11361,2139.57 h60
  text "PCB MUST BEAR THE UL94V-0 UL REGISTERED MATERIAL ID NUMBER" at 11361,2023.5 h60
  text "ADDITIONAL REQUIREMENTS:" at 11333.46,1854.08 h60
  text "MICROSECTION:" at 11408.23,1746.95 h60
  text "YES" at 12313.96,1746.95 h60
  text "X" at 12593.5,1602.62 h60
  text "REQUIRED" at 13175.46,1602.62 h60
  text "BARE BOARD ELEC. TEST:" at 11408.23,1599.76 h60
  text "NONE" at 12713.96,1599.76 h60
  text "PER ORDER" at 13767.46,1599.76 h60
  text "XX MIL VIAS REQUIRE NON-CONDUCTIVE FILL AND PLANARIZE" at 11576.38,1394.82 h59
  text "XX MIL VIAS REQUIRE CONDUCTIVE FILL AND PLANARIZE" at 11584.38,1290.84 h60
  text "OUTER XX MIL TRACES REQUIRE 50 OHM SINGLE-ENDED IMPEDANCE" at 11583.39,1127.46 h58
  text "LAYER 2 & 3 (INNER LAYERS) XX MIL WIDE, XX MIL SPACE / TRACES REQUIRE 100 OHM DIFFERENTIAL IMPEDANCE" at 11575.39,891.74 h60
  text ".Layer_Name" at 577,-858.49 h60
M11 Gerber Information:
  lines w10: -292,-930.17 6308,-930.17 ; -292,-726.83 6310,-726.83 ; -292,-523.5 -292,-1133.5 3713,-1133.5 6310,-1133.5 6310,-523.5 -291.5,-523.5 -291.5,-1133.5 1284,-1133.5 ; 2173,-1133.5 2173,-523.5 ; 3440,-726.83 3440,-523.5 ; 4280,-726.83 4280,-523.5 ; 4902,-1140 4902,-937.17
  text "ALL ARTWORK VIEWED FROM TOP SIDE" at -228.5,-655.67 h60
  text "BOARD #:" at 2248,-655.67 h60
  text ".PRJ_Number" at 2793.5,-655.67 h60
  text "REV:" at 3638,-655.67 h60
  text ".PCB_Rev" at 3929.5,-655.67 h60
  text "SVN REV:" at 4476,-655.67 h60
  text ".VersionControl_RevNumber" at 4982,-655.67 h60
  text "LAYER NAME =" at -228.5,-858.49 h60
  text "TID #:" at 2248,-859 h60
  text ".TID" at 2793.5,-859 h60
  text "PLOT NAME =" at -228.5,-1064.34 h60
  text ".plot_File_Name" at 577,-1064.34 h60
  text "GENERATED    :" at 2250,-1064.34 h60
  text ".Print_Date" at 3119.5,-1064.34 h60
  text ".Print_Time" at 3848.5,-1064.34 h60
  text "TEXAS INSTRUMENTS" at 5113,-1064.34 h60
M12 Stackup:
  drawing of 191 lines, arcs and shapes, not listed
  text "Layer" at 9760.58,7397.5 h60
  text "Name" at 10170.49,7397.5 h60
  text "Material" at 11100.23,7397.5 h60
  text "Thickness" at 11960,7397.5 h60
  text "Constant" at 12609.84,7397.5 h60
  text "Board Layer Stack" at 13179.7,7397.5 h60
  text "1" at 9760.58,7277.5 h60
  text "Top Overlay" at 10170.49,7277.5 h60
  text "2" at 9760.58,7157.5 h60
  text "Top Solder" at 10170.49,7157.5 h60
  text "Solder Resist" at 11100.23,7157.5 h60
  text "0.40mil" at 11960,7157.5 h60
  text "3.5" at 12609.84,7157.5 h60
  text "3" at 9760.58,7037.5 h60
  text "Top Layer" at 10170.49,7037.5 h60
  text "Copper" at 11100.23,7037.5 h60
  text "2.80mil" at 11960,7037.5 h60
  text "4" at 9760.58,6917.5 h60
  text "Dielectric1" at 10170.49,6917.5 h60
  text "FR-4" at 11100.23,6917.5 h60
  text "87.20mil" at 11960,6917.5 h60
  text "4.8" at 12609.84,6917.5 h60
  text "5" at 9760.58,6797.5 h60
  text "Bottom Layer" at 10170.49,6797.5 h60
  text "Copper" at 11100.23,6797.5 h60
  text "2.80mil" at 11960,6797.5 h60
  text "6" at 9760.58,6677.5 h60
  text "Bottom Solder" at 10170.49,6677.5 h60
  text "Solder Resist" at 11100.23,6677.5 h60
  text "0.40mil" at 11960,6677.5 h60
  text "3.5" at 12609.84,6677.5 h60
  text "7" at 9760.58,6557.5 h60
  text "Bottom Overlay" at 10170.49,6557.5 h60
  text ".Layer_Name" at 577,-858.49 h60
M13 Component Bodies Top:
  text ".Layer_Name" at 577,-858.49 h60
M14 Component Bodies Bottom:
  text ".Layer_Name" at 577,-858.49 h60
M15 Courtyards Top:
  text ".Layer_Name" at 577,-858.49 h60
M16 Courtyards Bottom:
  text ".Layer_Name" at 577,-858.49 h60
Drill Drawing:
  drawing of 184 lines, arcs and shapes, not listed
  text "Symbol" at 7996.57,3595.92 h72
  text "Quantity" at 8297.14,3595.92 h72
  text "Finished Hole Size" at 8629.14,3595.92 h72
  text "Plated" at 9265.7,3595.92 h72
  text "Hole Type" at 9524.84,3595.92 h72
  text "Drill Layer Pair" at 9900,3595.92 h72
  text "Hole Tolerance" at 10624.33,3595.92 h72
  text "4" at 8297.14,3471.6 h60
  text "98.43mil (2.500mm)" at 8629.14,3471.6 h60
  text "NPTH" at 9265.7,3471.6 h60
  text "Round" at 9524.84,3471.6 h60
  text "Top Layer - Bottom Layer" at 9900,3471.6 h60
  text "2" at 8297.14,3347.28 h60
  text "160.00mil (4.064mm)" at 8629.14,3347.28 h60
  text "NPTH" at 9265.7,3347.28 h60
  text "Round" at 9524.84,3347.28 h60
  text "Top Layer - Bottom Layer" at 9900,3347.28 h60
  text "B" at 7971.29,3337.29 h55.25
  text "3" at 8297.14,3222.96 h60
  text "254.00mil (6.452mm)" at 8629.14,3222.96 h60
  text "NPTH" at 9265.7,3222.96 h60
  text "Round" at 9524.84,3222.96 h60
  text "Top Layer - Bottom Layer" at 9900,3222.96 h60
  text "C" at 7971.29,3212.97 h55.25
  text "2" at 8297.14,3098.64 h60
  text "301.00mil (7.645mm)" at 8629.14,3098.64 h60
  text "NPTH" at 9265.7,3098.64 h60
  text "Round" at 9524.84,3098.64 h60
  text "Top Layer - Bottom Layer" at 9900,3098.64 h60
  text "1136" at 8297.14,2974.32 h60
  text "16.00mil (0.406mm)" at 8629.14,2974.32 h60
  text "PTH" at 9265.7,2974.32 h60
  text "Round" at 9524.84,2974.32 h60
  text "Top Layer - Bottom Layer" at 9900,2974.32 h60
  text "36" at 8297.14,2850 h60
  text "28.00mil (0.711mm)" at 8629.14,2850 h60
  text "PTH" at 9265.7,2850 h60
  text "Round" at 9524.84,2850 h60
  text "Top Layer - Bottom Layer" at 9900,2850 h60
  text "38" at 8297.14,2725.68 h60
  text "35.04mil (0.890mm)" at 8629.14,2725.68 h60
  text "PTH" at 9265.7,2725.68 h60
  text "Round" at 9524.84,2725.68 h60
  text "Top Layer - Bottom Layer" at 9900,2725.68 h60
  text "12" at 8297.14,2601.36 h60
  text "37.99mil (0.965mm)" at 8629.14,2601.36 h60
  text "PTH" at 9265.7,2601.36 h60
  text "Round" at 9524.84,2601.36 h60
  text "Top Layer - Bottom Layer" at 9900,2601.36 h60
  text "8" at 8297.14,2477.04 h60
  text "39.37mil (1.000mm)" at 8629.14,2477.04 h60
  text "PTH" at 9265.7,2477.04 h60
  text "Round" at 9524.84,2477.04 h60
  text "Top Layer - Bottom Layer" at 9900,2477.04 h60
  text "22" at 8297.14,2352.72 h60
  text "40.16mil (1.020mm)" at 8629.14,2352.72 h60
  text "PTH" at 9265.7,2352.72 h60
  text "Round" at 9524.84,2352.72 h60
  text "Top Layer - Bottom Layer" at 9900,2352.72 h60
  text "40" at 8297.14,2228.4 h60
  text "40.16mil (1.020mm)" at 8629.14,2228.4 h60
  text "PTH" at 9265.7,2228.4 h60
  text "Round" at 9524.84,2228.4 h60
  text "Top Layer - Bottom Layer" at 9900,2228.4 h60
  text "+/-7.87mil" at 10624.33,2228.4 h60
  text "52" at 8297.14,2104.08 h60
  text "40.95mil (1.040mm)" at 8629.14,2104.08 h60
  text "PTH" at 9265.7,2104.08 h60
  text "Round" at 9524.84,2104.08 h60
  text "Top Layer - Bottom Layer" at 9900,2104.08 h60
  text "4" at 8297.14,1979.76 h60
  text "41.34mil (1.050mm)" at 8629.14,1979.76 h60
  text "PTH" at 9265.7,1979.76 h60
  text "Round" at 9524.84,1979.76 h60
  text "Top Layer - Bottom Layer" at 9900,1979.76 h60
  text "28" at 8297.14,1855.44 h60
  text "62.99mil (1.600mm)" at 8629.14,1855.44 h60
  text "PTH" at 9265.7,1855.44 h60
  text "Round" at 9524.84,1855.44 h60
  text "Top Layer - Bottom Layer" at 9900,1855.44 h60
  text "4" at 8297.14,1731.12 h60
  text "86.61mil (2.200mm)" at 8629.14,1731.12 h60
  text "PTH" at 9265.7,1731.12 h60
  text "Round" at 9524.84,1731.12 h60
  text "Top Layer - Bottom Layer" at 9900,1731.12 h60
  text "1" at 8297.14,1606.8 h60
  text "160.00mil (4.064mm)" at 8629.14,1606.8 h60
  text "PTH" at 9265.7,1606.8 h60
  text "Round" at 9524.84,1606.8 h60
  text "Top Layer - Bottom Layer" at 9900,1606.8 h60
  text "6" at 8297.14,1482.48 h60
  text "254.00mil (6.452mm)" at 8629.14,1482.48 h60
  text "PTH" at 9265.7,1482.48 h60
  text "Round" at 9524.84,1482.48 h60
  text "Top Layer - Bottom Layer" at 9900,1482.48 h60
  text "1398 Total" at 8297.14,1358.16 h60
  text ".Layer_Name" at 577,-858.49 h60
M17 Embedded Cavity:
  text ".Layer_Name" at 577,-858.49 h60
M18 Embedded Assembly:
  text ".Layer_Name" at 577,-858.49 h60
M19 Embedded Keepout:
  text ".Layer_Name" at 577,-858.49 h60

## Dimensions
0,0 to 7000,0 on M2 Board Dimensions
0,-400 to 1000,-400 on M2 Board Dimensions
0,5200 to 6700,0 on M2 Board Dimensions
